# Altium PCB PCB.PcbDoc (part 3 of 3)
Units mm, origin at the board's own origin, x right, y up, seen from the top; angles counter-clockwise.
Board outline 120 x 100 mm, 4 copper layers (Top Layer, Mid-Layer 1, Mid-Layer 2, Bottom Layer); 85 components, 69 nets, 423 pads, 4470 vias.
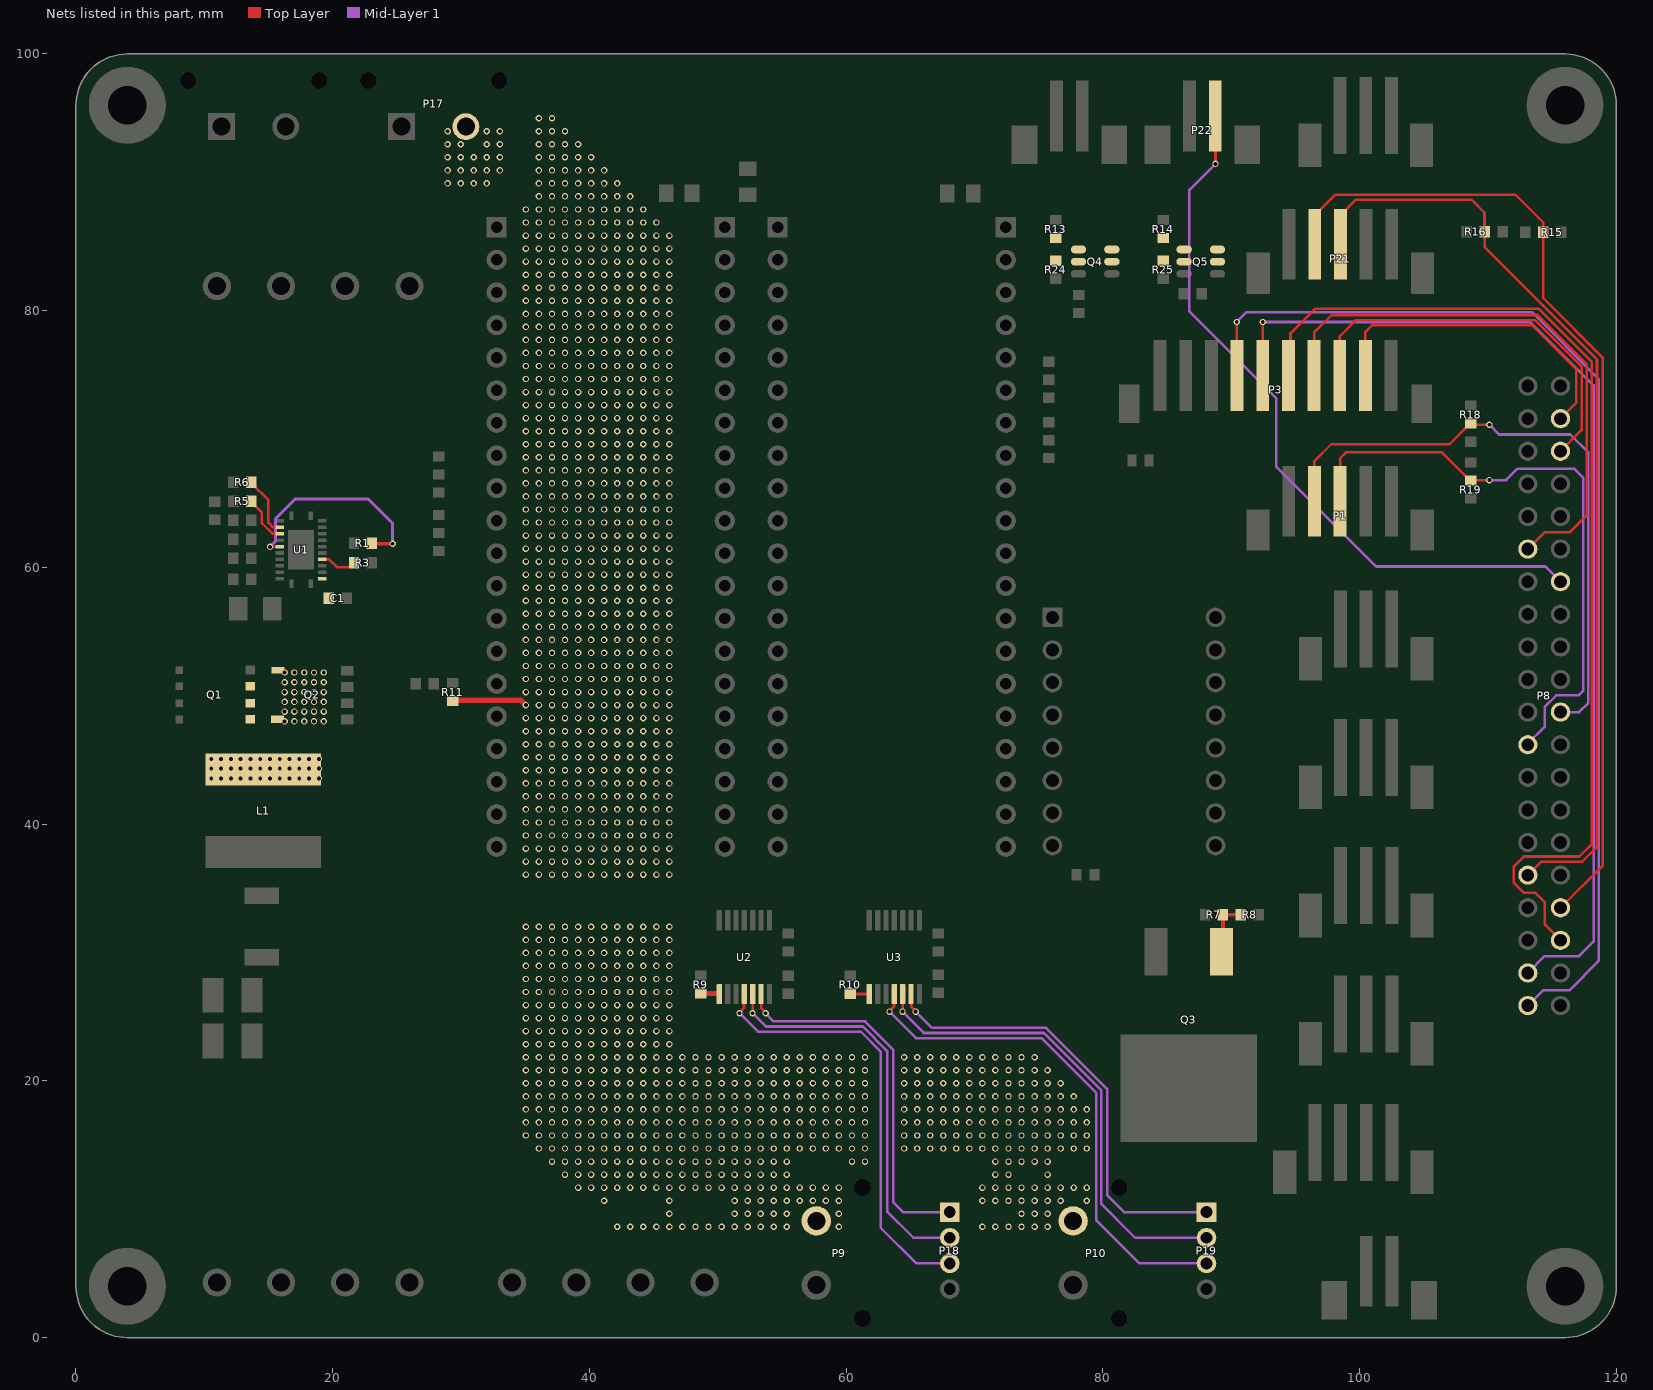
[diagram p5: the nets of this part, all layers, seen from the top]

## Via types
v1: diameter 0.5, hole 0.3, Top Layer to Bottom Layer, 4470 vias

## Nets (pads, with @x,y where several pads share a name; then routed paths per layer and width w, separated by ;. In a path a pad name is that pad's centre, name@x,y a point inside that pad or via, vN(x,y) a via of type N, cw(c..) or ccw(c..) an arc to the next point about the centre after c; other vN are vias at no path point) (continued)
NetQ3_1: Q3.1 R7.1 R8.2 | length 4.3
  Top Layer w0.3: Q3.1@89.23,30.071 89.346,30.187 R7.1@89.346,32.944 R8.2@90.74,32.944
NetQ4_1: Q4.1 Q4.2 Q4.5 Q4.6 R13.1 R24.2
NetQ5_1: Q5.1 Q5.2 Q5.5 Q5.6 R14.1 R25.1
NetR1_2: R1.2 U1.6 | length 16.9
  Top Layer w0.2: v1(15.113,61.595) 15.128,61.61 15.865,61.61 U1.6@15.88,61.626
  Top Layer w0.25: R1.2@23.052,61.874 23.077,61.9 23.128,61.849 v1(24.663,61.849)
  Mid-Layer 1 w0.25: v1(15.113,61.595) 15.545,62.027 15.545,63.805 17.069,65.329 22.758,65.329 24.663,63.424 v1(24.663,61.849)
NetR3_1: R3.1 U1.17 | length 2.8
  Top Layer w0.2: U1.17@19.195,60.626 19.714,60.626 20.32,60.02 21.322,60.02 R3.1@21.652,60.35
NetR5_1: R5.1 U1.4 | length 3.8
  Top Layer w0.2: R5.1@13.654,65.153 13.654,65.103 14.478,64.279 14.478,63.442 15.294,62.626 U1.4@15.88,62.626
NetR6_1: R6.1 U1.3 | length 4.7
  Top Layer w0.2: R6.1@13.654,66.627 13.654,66.577 14.986,65.245 14.986,63.5 15.36,63.126 U1.3@15.88,63.126
NetR9_1: R9.1 U2.8 | length 1.5
  Top Layer w0.4: R9.1@48.666,26.808 50.115,26.808 50.12,26.803 U2.8@50.12,26.772
NetR10_1: R10.1 U3.8 | length 1.5
  Top Layer w0.25: R10.1@60.325,26.783 60.336,26.772 U3.8@61.804,26.772
RSPI5_GPIO8: P1.3 P8.24 R19.1 | length 47.7
  Top Layer w0.2: P1.3@98.477,65.168 98.477,68.505 98.933,68.961 106.415,68.961 108.611,66.765 R19.1@108.661,66.765 108.698,66.802 v1(110.109,66.802)
  Mid-Layer 1 w0.2: v1(110.109,66.802) 111.42,66.802 112.309,67.691 116.713,67.691 117.424,66.98 117.424,50.419 117.043,50.038 115.316,50.038 114.427,49.149 114.427,47.625 113.106,46.304 P8.24@113.106,46.19
RSPI5_GPIO9: P1.4 P8.21 R18.1 | length 48.6
  Top Layer w0.2: P1.4@96.477,65.168 96.477,68.283 97.79,69.596 107,69.596 108.611,71.208 R18.1@108.661,71.208 108.749,71.12 v1(110.109,71.12)
  Mid-Layer 1 w0.2: v1(110.109,71.12) 110.871,70.358 116.408,70.358 117.824,68.942 117.824,49.447 117.107,48.73 P8.21@115.646,48.73
RSPI5_GPIO12: P8.32 P21.3 R16.1 | length 73.7
  Top Layer w0.2: P21.3@98.501,85.168 98.501,87.418 99.729,88.646 108.712,88.646 109.728,87.63 109.728,86.171 R16.1@109.742,86.157 109.742,84.949 118.491,76.2 118.491,72.853 118.491,38.227 117.343,37.079 114.155,37.079 P8.32@113.106,36.03
RSPI5_GPIO13: P8.33 P21.4 R15.1 | length 78.3
  Top Layer w0.2: P21.4@96.501,85.168 96.501,87.418 98.129,89.046 112.122,89.046 114.303,86.865 R15.1@114.303,86.106 114.303,80.972 118.948,76.327 118.948,36.792 P8.33@115.646,33.49
RSPI5_GPIO18: P3.4 P8.12 | length 44.2
  Top Layer w0.2: P3.4@96.451,74.954 96.451,78.29 97.828,79.667 113.856,79.667 117.691,75.832 117.691,64.046 116.396,62.751 114.427,62.751 P8.12@113.106,61.43
RSPI5_GPIO19: P3.5 P8.35 | length 81.5
  Top Layer w0.2: P3.5@94.451,74.954 94.615,75.117 94.615,78.232 96.52,80.137 113.97,80.137 118.091,76.016 118.091,38.462 117.108,37.479 112.79,37.479 112.014,36.703 112.014,35.433 112.801,34.646 113.69,34.646 114.427,33.909 114.427,32.169 P8.35@115.646,30.95
RSPI5_GPIO20: P3.6 P8.38 | length 81.4
  Top Layer w0.2: P3.6@92.451,74.954 92.456,74.958 v1(92.456,79.121)
  Mid-Layer 1 w0.2: v1(92.456,79.121) 113.284,79.121 118.224,74.181 118.224,30.848 117.094,29.718 114.414,29.718 P8.38@113.106,28.41
RSPI5_GPIO21: P3.7 P8.40 | length 87.1
  Top Layer w0.2: v1(90.424,79.121) 90.424,74.981 P3.7@90.449,74.955
  Mid-Layer 1 w0.2: v1(90.424,79.121) 91.186,79.883 113.411,79.883 118.624,74.67 118.624,29.343 116.332,27.051 114.287,27.051 P8.40@113.106,25.87
RSPI5_SCL: P3.3 P8.5 | length 31.2
  Top Layer w0.2: P3.3@98.451,74.954 98.451,78.004 99.714,79.267 113.671,79.267 117.291,75.647 117.291,70.695 P8.5@115.646,69.05
RSPI5_SDA: P3.2 P8.3 | length 25.8
  Top Layer w0.2: P3.2@100.451,74.954 100.451,78.353 100.965,78.867 113.436,78.867 116.891,75.412 116.891,72.835 P8.3@115.646,71.59
SERVO_X_GPIO_4: P18.3 U2.11 | length 34.1
  Top Layer w0.2: v1@51.689,25.336 52.04,25.687 U2.11@52.04,26.772
  Mid-Layer 1 w0.2: v1(51.689,25.273) 53.124,23.838 61.137,23.838 62.687,22.287 62.687,8.56 65.465,5.782 P18.3@68.072,5.782
SERVO_X_GPIO_11: P18.1 U2.13 | length 29.4
  Top Layer w0.2: U2.13@53.37,26.772 53.37,25.687 53.721,25.336 v1(53.721,25.273)
  Mid-Layer 1 w0.2: v1(53.721,25.273) 54.356,24.638 61.468,24.638 63.665,22.441 63.665,10.554 64.437,9.782 P18.1@68.072,9.782
SERVO_X_GPIO_12: P18.2 U2.12 | length 31.4
  Top Layer w0.2: v1(52.705,25.273) 52.713,25.281 52.713,26.764 U2.12@52.72,26.772
  Mid-Layer 1 w0.2: v1(52.705,25.273) 53.74,24.238 61.302,24.238 63.195,22.345 63.195,9.83 65.243,7.782 P18.2@68.072,7.782
SERVO_Y_GPIO_5: P19.3 U3.11 | length 40.2
  Top Layer w0.2: v1@63.373,25.463 63.724,25.814 U3.11@63.724,26.899
  Mid-Layer 1 w0.2: v1(63.373,25.4) 65.443,23.33 75.234,23.33 79.477,19.087 79.477,9.169 82.864,5.782 P19.3@88.072,5.782
SERVO_Y_GPIO_13: P19.1 U3.13 | length 35.6
  Top Layer w0.2: U3.13@65.054,26.899 U3.13@65.054,26.772 65.054,25.814 v1@65.405,25.463
  Mid-Layer 1 w0.2: v1(65.405,25.4) 66.675,24.13 75.565,24.13 80.327,19.368 80.327,11.113 81.658,9.782 P19.1@88.072,9.782
SERVO_Y_GPIO_14: P19.2 U3.12 | length 37.6
  Top Layer w0.2: v1@64.397,25.408 U3.12@64.397,26.891
  Mid-Layer 1 w0.2: v1(64.389,25.4) 66.059,23.73 75.399,23.73 79.883,19.246 79.883,10.414 82.515,7.782 P19.2@88.072,7.782
SHTDOWN_RSPI5_GPIO27: P8.13 P22.1 | length 56.8
  Top Layer w0.2: P22.1@88.752,95.168 88.773,95.147 v1(88.773,91.44)
  Mid-Layer 1 w0.2: v1(88.773,91.44) 86.741,89.408 86.741,79.941 93.491,73.191 93.491,67.857 101.277,60.071 114.465,60.071 P8.13@115.646,58.89
SW: C1.1 L1.1 Q1.1 Q1.2 Q1.3 Q2.5 Q2.6 U1.14
  other v1: 10.541,43.561 11.303,43.561 12.065,43.561 12.827,43.561 13.589,43.561 14.351,43.561 15.113,43.561 15.875,43.561 16.637,43.561 17.399,43.561 18.161,43.561 18.923,43.561 10.541,44.323 11.303,44.323 12.065,44.323 12.827,44.323 13.589,44.323 14.351,44.323 15.113,44.323 15.875,44.323 16.637,44.323 17.399,44.323 18.161,44.323 18.923,44.323 10.541,45.085 11.303,45.085 12.065,45.085 12.827,45.085 13.589,45.085 14.351,45.085 15.113,45.085 15.875,45.085 16.637,45.085 17.399,45.085 18.161,45.085 18.923,45.085 16.256,48.006 17.018,48.006 17.78,48.006 18.542,48.006 19.304,48.006 16.256,48.768 17.018,48.768 17.78,48.768 18.542,48.768 19.304,48.768 16.256,49.53 17.018,49.53 17.78,49.53 18.542,49.53 19.304,49.53 16.256,50.292 17.018,50.292 17.78,50.292 18.542,50.292 19.304,50.292 16.256,51.054 17.018,51.054 17.78,51.054 18.542,51.054 19.304,51.054 16.256,51.816 17.018,51.816 17.78,51.816 18.542,51.816 19.304,51.816
VIN_40V: P9.1 P10.1 P17.2 R11.2 | length 5.9
  Top Layer w0.4: R11.2@29.337,49.657 34.671,49.657 v1(35.052,49.276)
  other v1: 42.164,8.636 43.18,8.636 44.196,8.636 45.212,8.636 46.228,8.636 47.244,8.636 48.26,8.636 49.276,8.636 50.292,8.636 51.308,8.636 52.324,8.636 53.34,8.636 54.356,8.636 55.372,8.636 59.436,8.636 70.612,8.636 71.628,8.636 72.644,8.636 73.66,8.636 74.676,8.636 75.692,8.636 46.228,9.652 51.308,9.652 52.324,9.652 53.34,9.652 54.356,9.652 55.372,9.652 59.436,9.652 73.66,9.652 74.676,9.652 75.692,9.652 41.148,10.668 46.228,10.668 51.308,10.668 52.324,10.668 53.34,10.668 54.356,10.668 55.372,10.668 56.388,10.668 57.404,10.668 58.42,10.668 59.436,10.668 70.612,10.668 71.628,10.668 72.644,10.668 73.66,10.668 74.676,10.668 75.692,10.668 76.708,10.668 78.74,10.668 39.116,11.684 40.132,11.684 41.148,11.684 42.164,11.684 43.18,11.684 44.196,11.684 45.212,11.684 46.228,11.684 47.244,11.684 48.26,11.684 49.276,11.684 50.292,11.684 51.308,11.684 52.324,11.684 53.34,11.684 54.356,11.684 55.372,11.684 56.388,11.684 57.404,11.684 58.42,11.684 59.436,11.684 70.612,11.684 71.628,11.684 72.644,11.684 73.66,11.684 74.676,11.684 75.692,11.684 76.708,11.684 77.724,11.684 78.74,11.684 38.1,12.7 39.116,12.7 40.132,12.7 41.148,12.7 42.164,12.7 43.18,12.7 44.196,12.7 45.212,12.7 46.228,12.7 47.244,12.7 48.26,12.7 49.276,12.7 50.292,12.7 51.308,12.7 52.324,12.7 53.34,12.7 54.356,12.7 55.372,12.7 71.628,12.7 72.644,12.7 75.692,12.7 37.084,13.716 38.1,13.716 39.116,13.716 40.132,13.716 41.148,13.716 42.164,13.716 43.18,13.716 44.196,13.716 45.212,13.716 46.228,13.716 47.244,13.716 48.26,13.716 49.276,13.716 50.292,13.716 51.308,13.716 52.324,13.716 53.34,13.716 54.356,13.716 55.372,13.716 60.452,13.716 61.468,13.716 71.628,13.716 72.644,13.716 73.66,13.716 74.676,13.716 75.692,13.716 36.068,14.732 37.084,14.732 38.1,14.732 39.116,14.732 40.132,14.732 41.148,14.732 42.164,14.732 43.18,14.732 44.196,14.732 45.212,14.732 46.228,14.732 47.244,14.732 48.26,14.732 49.276,14.732 50.292,14.732 51.308,14.732 52.324,14.732 53.34,14.732 54.356,14.732 55.372,14.732 56.388,14.732 57.404,14.732 58.42,14.732 59.436,14.732 60.452,14.732 61.468,14.732 64.516,14.732 65.532,14.732 66.548,14.732 67.564,14.732 68.58,14.732 69.596,14.732 70.612,14.732 71.628,14.732 72.644,14.732 73.66,14.732 74.676,14.732 75.692,14.732 76.708,14.732 77.724,14.732 78.74,14.732 35.052,15.748 36.068,15.748 37.084,15.748 38.1,15.748 39.116,15.748 40.132,15.748 41.148,15.748 42.164,15.748 43.18,15.748 44.196,15.748 45.212,15.748 46.228,15.748 47.244,15.748 48.26,15.748 49.276,15.748 50.292,15.748 51.308,15.748 52.324,15.748 53.34,15.748 54.356,15.748 55.372,15.748 56.388,15.748 57.404,15.748 58.42,15.748 59.436,15.748 60.452,15.748 61.468,15.748 64.516,15.748 65.532,15.748 66.548,15.748 67.564,15.748 68.58,15.748 69.596,15.748 70.612,15.748 71.628,15.748 72.644,15.748 73.66,15.748 74.676,15.748 75.692,15.748 76.708,15.748 77.724,15.748 78.74,15.748 35.052,16.764 36.068,16.764 37.084,16.764 38.1,16.764 39.116,16.764 40.132,16.764 41.148,16.764 42.164,16.764 43.18,16.764 44.196,16.764 45.212,16.764 46.228,16.764 47.244,16.764 48.26,16.764 49.276,16.764 50.292,16.764 51.308,16.764 52.324,16.764 53.34,16.764 54.356,16.764 55.372,16.764 56.388,16.764 57.404,16.764 58.42,16.764 59.436,16.764 60.452,16.764 61.468,16.764 64.516,16.764 65.532,16.764 66.548,16.764 67.564,16.764 68.58,16.764 69.596,16.764 70.612,16.764 71.628,16.764 72.644,16.764 73.66,16.764 74.676,16.764 75.692,16.764 76.708,16.764 77.724,16.764 78.74,16.764 35.052,17.78 36.068,17.78 37.084,17.78 38.1,17.78 39.116,17.78 40.132,17.78 41.148,17.78 42.164,17.78 43.18,17.78 44.196,17.78 45.212,17.78 46.228,17.78 47.244,17.78 48.26,17.78 49.276,17.78 50.292,17.78 51.308,17.78 52.324,17.78 53.34,17.78 54.356,17.78 55.372,17.78 56.388,17.78 57.404,17.78 58.42,17.78 59.436,17.78 60.452,17.78 61.468,17.78 64.516,17.78 65.532,17.78 66.548,17.78 67.564,17.78 68.58,17.78 69.596,17.78 70.612,17.78 71.628,17.78 72.644,17.78 73.66,17.78 74.676,17.78 75.692,17.78 76.708,17.78 77.724,17.78 78.74,17.78 35.052,18.796 36.068,18.796 37.084,18.796 38.1,18.796 39.116,18.796 40.132,18.796 41.148,18.796 42.164,18.796 43.18,18.796 44.196,18.796 45.212,18.796 46.228,18.796 47.244,18.796 48.26,18.796 49.276,18.796 50.292,18.796 51.308,18.796 52.324,18.796 53.34,18.796 54.356,18.796 55.372,18.796 56.388,18.796 57.404,18.796 58.42,18.796 59.436,18.796 60.452,18.796 61.468,18.796 64.516,18.796 65.532,18.796 66.548,18.796 67.564,18.796 68.58,18.796 69.596,18.796 70.612,18.796 71.628,18.796 72.644,18.796 73.66,18.796 74.676,18.796 75.692,18.796 76.708,18.796 77.724,18.796 35.052,19.812 36.068,19.812 37.084,19.812 38.1,19.812 39.116,19.812 40.132,19.812 41.148,19.812 42.164,19.812 43.18,19.812 44.196,19.812 45.212,19.812 46.228,19.812 47.244,19.812 48.26,19.812 49.276,19.812 50.292,19.812 51.308,19.812 52.324,19.812 53.34,19.812 54.356,19.812 55.372,19.812 56.388,19.812 57.404,19.812 58.42,19.812 59.436,19.812 60.452,19.812 61.468,19.812 64.516,19.812 65.532,19.812 66.548,19.812 67.564,19.812 68.58,19.812 69.596,19.812 70.612,19.812 71.628,19.812 72.644,19.812 73.66,19.812 74.676,19.812 75.692,19.812 76.708,19.812 35.052,20.828 36.068,20.828 37.084,20.828 38.1,20.828 39.116,20.828 40.132,20.828 41.148,20.828 42.164,20.828 43.18,20.828 44.196,20.828 45.212,20.828 46.228,20.828 47.244,20.828 48.26,20.828 49.276,20.828 50.292,20.828 51.308,20.828 52.324,20.828 53.34,20.828 54.356,20.828 55.372,20.828 56.388,20.828 57.404,20.828 58.42,20.828 59.436,20.828 60.452,20.828 61.468,20.828 64.516,20.828 65.532,20.828 66.548,20.828 67.564,20.828 68.58,20.828 69.596,20.828 70.612,20.828 71.628,20.828 72.644,20.828 73.66,20.828 74.676,20.828 75.692,20.828 35.052,21.844 36.068,21.844 37.084,21.844 38.1,21.844 39.116,21.844 40.132,21.844 41.148,21.844 42.164,21.844 43.18,21.844 44.196,21.844 45.212,21.844 46.228,21.844 47.244,21.844 48.26,21.844 49.276,21.844 50.292,21.844 51.308,21.844 52.324,21.844 53.34,21.844 54.356,21.844 55.372,21.844 56.388,21.844 57.404,21.844 58.42,21.844 59.436,21.844 60.452,21.844 61.468,21.844 64.516,21.844 65.532,21.844 66.548,21.844 67.564,21.844 68.58,21.844 69.596,21.844 70.612,21.844 71.628,21.844 72.644,21.844 73.66,21.844 74.676,21.844 35.052,22.86 36.068,22.86 37.084,22.86 38.1,22.86 39.116,22.86 40.132,22.86 41.148,22.86 42.164,22.86 43.18,22.86 44.196,22.86 45.212,22.86 46.228,22.86 35.052,23.876 36.068,23.876 37.084,23.876 38.1,23.876 39.116,23.876 40.132,23.876 41.148,23.876 42.164,23.876 43.18,23.876 44.196,23.876 45.212,23.876 46.228,23.876 35.052,24.892 36.068,24.892 37.084,24.892 38.1,24.892 39.116,24.892 40.132,24.892 41.148,24.892 42.164,24.892 43.18,24.892 44.196,24.892 45.212,24.892 46.228,24.892 35.052,25.908 36.068,25.908 37.084,25.908 38.1,25.908 39.116,25.908 40.132,25.908 41.148,25.908 42.164,25.908 43.18,25.908 44.196,25.908 45.212,25.908 46.228,25.908 35.052,26.924 36.068,26.924 37.084,26.924 38.1,26.924 39.116,26.924 40.132,26.924 41.148,26.924 42.164,26.924 43.18,26.924 44.196,26.924 45.212,26.924 46.228,26.924 35.052,27.94 36.068,27.94 37.084,27.94 38.1,27.94 39.116,27.94 40.132,27.94 41.148,27.94 42.164,27.94 43.18,27.94 44.196,27.94 45.212,27.94 46.228,27.94 35.052,28.956 36.068,28.956 37.084,28.956 38.1,28.956 39.116,28.956 40.132,28.956 41.148,28.956 42.164,28.956 43.18,28.956 44.196,28.956 45.212,28.956 46.228,28.956 35.052,29.972 36.068,29.972 37.084,29.972 38.1,29.972 39.116,29.972 40.132,29.972 41.148,29.972 42.164,29.972 43.18,29.972 44.196,29.972 45.212,29.972 46.228,29.972 35.052,30.988 36.068,30.988 37.084,30.988 38.1,30.988 39.116,30.988 40.132,30.988 41.148,30.988 42.164,30.988 43.18,30.988 44.196,30.988 45.212,30.988 46.228,30.988 35.052,32.004 36.068,32.004 37.084,32.004 38.1,32.004 39.116,32.004 40.132,32.004 41.148,32.004 42.164,32.004 43.18,32.004 44.196,32.004 45.212,32.004 46.228,32.004 35.052,36.068 36.068,36.068 37.084,36.068 38.1,36.068 39.116,36.068 40.132,36.068 41.148,36.068 42.164,36.068 43.18,36.068 44.196,36.068 45.212,36.068 46.228,36.068 35.052,37.084 36.068,37.084 37.084,37.084 38.1,37.084 39.116,37.084 40.132,37.084 41.148,37.084 42.164,37.084 43.18,37.084 44.196,37.084 45.212,37.084 46.228,37.084 35.052,38.1 36.068,38.1 37.084,38.1 38.1,38.1 39.116,38.1 40.132,38.1 41.148,38.1 42.164,38.1 43.18,38.1 44.196,38.1 45.212,38.1 46.228,38.1 35.052,39.116 36.068,39.116 37.084,39.116 38.1,39.116 39.116,39.116 40.132,39.116 41.148,39.116 42.164,39.116 43.18,39.116 44.196,39.116 45.212,39.116 46.228,39.116 35.052,40.132 36.068,40.132 37.084,40.132 38.1,40.132 39.116,40.132 40.132,40.132 41.148,40.132 42.164,40.132 43.18,40.132 44.196,40.132 45.212,40.132 46.228,40.132 35.052,41.148 36.068,41.148 37.084,41.148 38.1,41.148 39.116,41.148 40.132,41.148 41.148,41.148 42.164,41.148 43.18,41.148 44.196,41.148 45.212,41.148 46.228,41.148 35.052,42.164 36.068,42.164 37.084,42.164 38.1,42.164 39.116,42.164 40.132,42.164 41.148,42.164 42.164,42.164 43.18,42.164 44.196,42.164 45.212,42.164 46.228,42.164 35.052,43.18 36.068,43.18 37.084,43.18 38.1,43.18 39.116,43.18 40.132,43.18 41.148,43.18 42.164,43.18 43.18,43.18 44.196,43.18 45.212,43.18 46.228,43.18 35.052,44.196 36.068,44.196 37.084,44.196 38.1,44.196 39.116,44.196 40.132,44.196 41.148,44.196 42.164,44.196 43.18,44.196 44.196,44.196 45.212,44.196 46.228,44.196 35.052,45.212 36.068,45.212 37.084,45.212 38.1,45.212 39.116,45.212 40.132,45.212 41.148,45.212 42.164,45.212 43.18,45.212 44.196,45.212 45.212,45.212 46.228,45.212 35.052,46.228 36.068,46.228 37.084,46.228 38.1,46.228 39.116,46.228 40.132,46.228 41.148,46.228 42.164,46.228 43.18,46.228 44.196,46.228 45.212,46.228 46.228,46.228 35.052,47.244 36.068,47.244 37.084,47.244 38.1,47.244 39.116,47.244 40.132,47.244 41.148,47.244 42.164,47.244 43.18,47.244 44.196,47.244 45.212,47.244 46.228,47.244 35.052,48.26 36.068,48.26 37.084,48.26 38.1,48.26 39.116,48.26 40.132,48.26 41.148,48.26 42.164,48.26 43.18,48.26 44.196,48.26 45.212,48.26 46.228,48.26 36.068,49.276 37.084,49.276 38.1,49.276 39.116,49.276 40.132,49.276 41.148,49.276 42.164,49.276 43.18,49.276 44.196,49.276 45.212,49.276 46.228,49.276 35.052,50.292 36.068,50.292 37.084,50.292 38.1,50.292 39.116,50.292 40.132,50.292 41.148,50.292 42.164,50.292 43.18,50.292 44.196,50.292 45.212,50.292 46.228,50.292 35.052,51.308 36.068,51.308 37.084,51.308 38.1,51.308 39.116,51.308 40.132,51.308 41.148,51.308 42.164,51.308 43.18,51.308 44.196,51.308 45.212,51.308 46.228,51.308 35.052,52.324 36.068,52.324 37.084,52.324 38.1,52.324 39.116,52.324 40.132,52.324 41.148,52.324 42.164,52.324 43.18,52.324 44.196,52.324 45.212,52.324 46.228,52.324 35.052,53.34 36.068,53.34 37.084,53.34 38.1,53.34 39.116,53.34 40.132,53.34 41.148,53.34 42.164,53.34 43.18,53.34 44.196,53.34 45.212,53.34 46.228,53.34 35.052,54.356 36.068,54.356 37.084,54.356 38.1,54.356 39.116,54.356 40.132,54.356 41.148,54.356 42.164,54.356 43.18,54.356 44.196,54.356 45.212,54.356 46.228,54.356 35.052,55.372 36.068,55.372 37.084,55.372 38.1,55.372 39.116,55.372 40.132,55.372 41.148,55.372 42.164,55.372 43.18,55.372 44.196,55.372 45.212,55.372 46.228,55.372 35.052,56.388 36.068,56.388 37.084,56.388 38.1,56.388 39.116,56.388 40.132,56.388 41.148,56.388 42.164,56.388 43.18,56.388 44.196,56.388 45.212,56.388 46.228,56.388 35.052,57.404 36.068,57.404 37.084,57.404 38.1,57.404 39.116,57.404 40.132,57.404 41.148,57.404 42.164,57.404 43.18,57.404 44.196,57.404 45.212,57.404 46.228,57.404 35.052,58.42 36.068,58.42 37.084,58.42 38.1,58.42 39.116,58.42 40.132,58.42 41.148,58.42 42.164,58.42 43.18,58.42 44.196,58.42 45.212,58.42 46.228,58.42 35.052,59.436 36.068,59.436 37.084,59.436 38.1,59.436 39.116,59.436 40.132,59.436 41.148,59.436 42.164,59.436 43.18,59.436 44.196,59.436 45.212,59.436 46.228,59.436 35.052,60.452 36.068,60.452 37.084,60.452 38.1,60.452 39.116,60.452 40.132,60.452 41.148,60.452 42.164,60.452 43.18,60.452 44.196,60.452 45.212,60.452 46.228,60.452 35.052,61.468 36.068,61.468 37.084,61.468 38.1,61.468 39.116,61.468 40.132,61.468 41.148,61.468 42.164,61.468 43.18,61.468 44.196,61.468 45.212,61.468 46.228,61.468 35.052,62.484 36.068,62.484 37.084,62.484 38.1,62.484 39.116,62.484 40.132,62.484 41.148,62.484 42.164,62.484 43.18,62.484 44.196,62.484 45.212,62.484 46.228,62.484 35.052,63.5 36.068,63.5 37.084,63.5 38.1,63.5 39.116,63.5 40.132,63.5 41.148,63.5 42.164,63.5 43.18,63.5 44.196,63.5 45.212,63.5 46.228,63.5 35.052,64.516 36.068,64.516 37.084,64.516 38.1,64.516 39.116,64.516 40.132,64.516 41.148,64.516 42.164,64.516 43.18,64.516 44.196,64.516 45.212,64.516 46.228,64.516 35.052,65.532 36.068,65.532 37.084,65.532 38.1,65.532 39.116,65.532 40.132,65.532 41.148,65.532 42.164,65.532 43.18,65.532 44.196,65.532 45.212,65.532 46.228,65.532 35.052,66.548 36.068,66.548 37.084,66.548 38.1,66.548 39.116,66.548 40.132,66.548 41.148,66.548 42.164,66.548 43.18,66.548 44.196,66.548 45.212,66.548 46.228,66.548 35.052,67.564 36.068,67.564 37.084,67.564 38.1,67.564 39.116,67.564 40.132,67.564 41.148,67.564 42.164,67.564 43.18,67.564 44.196,67.564 45.212,67.564 46.228,67.564 35.052,68.58 36.068,68.58 37.084,68.58 38.1,68.58 39.116,68.58 40.132,68.58 41.148,68.58 42.164,68.58 43.18,68.58 44.196,68.58 45.212,68.58 46.228,68.58 35.052,69.596 36.068,69.596 37.084,69.596 38.1,69.596 39.116,69.596 40.132,69.596 41.148,69.596 42.164,69.596 43.18,69.596 44.196,69.596 45.212,69.596 46.228,69.596 35.052,70.612 36.068,70.612 37.084,70.612 38.1,70.612 39.116,70.612 40.132,70.612 41.148,70.612 42.164,70.612 43.18,70.612 44.196,70.612 45.212,70.612 46.228,70.612 35.052,71.628 36.068,71.628 37.084,71.628 38.1,71.628 39.116,71.628 40.132,71.628 41.148,71.628 42.164,71.628 43.18,71.628 44.196,71.628 45.212,71.628 46.228,71.628 35.052,72.644 36.068,72.644 37.084,72.644 38.1,72.644 39.116,72.644 40.132,72.644 41.148,72.644 42.164,72.644 43.18,72.644 44.196,72.644 45.212,72.644 46.228,72.644 35.052,73.66 36.068,73.66 37.084,73.66 38.1,73.66 39.116,73.66 40.132,73.66 41.148,73.66 42.164,73.66 43.18,73.66 44.196,73.66 45.212,73.66 46.228,73.66 35.052,74.676 36.068,74.676 37.084,74.676 38.1,74.676 39.116,74.676 40.132,74.676 41.148,74.676 42.164,74.676 43.18,74.676 44.196,74.676 45.212,74.676 46.228,74.676 35.052,75.692 36.068,75.692 37.084,75.692 38.1,75.692 39.116,75.692 40.132,75.692 41.148,75.692 42.164,75.692 43.18,75.692 44.196,75.692 45.212,75.692 46.228,75.692 35.052,76.708 36.068,76.708 37.084,76.708 38.1,76.708 39.116,76.708 40.132,76.708 41.148,76.708 42.164,76.708 43.18,76.708 44.196,76.708 45.212,76.708 46.228,76.708 35.052,77.724 36.068,77.724 37.084,77.724 38.1,77.724 39.116,77.724 40.132,77.724 41.148,77.724 42.164,77.724 43.18,77.724 44.196,77.724 45.212,77.724 46.228,77.724 35.052,78.74 36.068,78.74 37.084,78.74 38.1,78.74 39.116,78.74 40.132,78.74 41.148,78.74 42.164,78.74 43.18,78.74 44.196,78.74 45.212,78.74 46.228,78.74 35.052,79.756 36.068,79.756 37.084,79.756 38.1,79.756 39.116,79.756 40.132,79.756 41.148,79.756 42.164,79.756 43.18,79.756 44.196,79.756 45.212,79.756 46.228,79.756 35.052,80.772 36.068,80.772 37.084,80.772 38.1,80.772 39.116,80.772 40.132,80.772 41.148,80.772 42.164,80.772 43.18,80.772 44.196,80.772 45.212,80.772 46.228,80.772 35.052,81.788 36.068,81.788 37.084,81.788 38.1,81.788 39.116,81.788 40.132,81.788 41.148,81.788 42.164,81.788 43.18,81.788 44.196,81.788 45.212,81.788 46.228,81.788 35.052,82.804 36.068,82.804 37.084,82.804 38.1,82.804 39.116,82.804 40.132,82.804 41.148,82.804 42.164,82.804 43.18,82.804 44.196,82.804 45.212,82.804 46.228,82.804 35.052,83.82 36.068,83.82 37.084,83.82 38.1,83.82 39.116,83.82 40.132,83.82 41.148,83.82 42.164,83.82 43.18,83.82 44.196,83.82 45.212,83.82 46.228,83.82 35.052,84.836 36.068,84.836 37.084,84.836 38.1,84.836 39.116,84.836 40.132,84.836 41.148,84.836 42.164,84.836 43.18,84.836 44.196,84.836 45.212,84.836 46.228,84.836 35.052,85.852 36.068,85.852 37.084,85.852 38.1,85.852 39.116,85.852 40.132,85.852 41.148,85.852 42.164,85.852 43.18,85.852 44.196,85.852 45.212,85.852 46.228,85.852 35.052,86.868 36.068,86.868 37.084,86.868 38.1,86.868 39.116,86.868 40.132,86.868 41.148,86.868 42.164,86.868 43.18,86.868 44.196,86.868 45.212,86.868 35.052,87.884 36.068,87.884 37.084,87.884 38.1,87.884 39.116,87.884 40.132,87.884 41.148,87.884 42.164,87.884 43.18,87.884 44.196,87.884 36.068,88.9 37.084,88.9 38.1,88.9 39.116,88.9 40.132,88.9 41.148,88.9 42.164,88.9 43.18,88.9 28.956,89.916 29.972,89.916 30.988,89.916 32.004,89.916 36.068,89.916 37.084,89.916 38.1,89.916 39.116,89.916 40.132,89.916 41.148,89.916 42.164,89.916 28.956,90.932 29.972,90.932 30.988,90.932 32.004,90.932 33.02,90.932 36.068,90.932 37.084,90.932 38.1,90.932 39.116,90.932 40.132,90.932 41.148,90.932 28.956,91.948 29.972,91.948 30.988,91.948 32.004,91.948 33.02,91.948 36.068,91.948 37.084,91.948 38.1,91.948 39.116,91.948 40.132,91.948 28.956,92.964 29.972,92.964 32.004,92.964 33.02,92.964 36.068,92.964 37.084,92.964 38.1,92.964 39.116,92.964 28.956,93.98 32.004,93.98 33.02,93.98 36.068,93.98 37.084,93.98 38.1,93.98 36.068,94.996 37.084,94.996
pads on no net: MOD1.1 MOD1.2 MOD1.3 MOD1.4 MOD1.5 MOD2.16 MOD2.17 MOD2.20 MOD2.21 MOD2.22 MOD2.24 MOD2.25 MOD2.29 MOD2.30 MOD2.31 MOD2.32 MOD2.34 MOD2.35 MOD2.37 MOD2.40 MOD3.1 MOD3.2 MOD3.4 MOD3.5 MOD3.6 MOD3.7 MOD3.9 MOD3.10 MOD3.11 MOD3.12 MOD3.14 MOD3.15 MOD3.19 MOD3.20 MOD3.21 MOD3.22 MOD3.24 MOD3.25 MOD3.26 MOD3.27 MOD3.29 MOD3.30 MOD3.31 MOD3.32 MOD3.36 MOD3.37 MOD3.40 P7. P8.11 P8.16 P8.17 P8.18 P8.19 P8.22 P8.23 P8.26 P8.27 P8.28 P8.31 P8.36 P8.37 P9. P10. P17. P21.MP U1.2 U1.22 U1.23 U2.5 U2.6 U2.9 U2.10 U3.5 U3.6 U3.9 U3.10

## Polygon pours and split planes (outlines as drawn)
GND on Top Layer "Top Layer-GND" (solid, pour order 2): 115.849,0.027 ccw(c115.849,4.089) 119.911,4.089 119.969,95.809 ccw(c115.861,95.918) 115.97,100.025 3.984,100.025 ccw(c3.979,96.021) -0.025,96.025 -0.025,4.089 ccw(c4.039,4.089) 4.039,0.025
GND on Mid-Layer 1 "Mid-Layer 1-GND" (solid, pour order 4): 115.863,0.002 ccw(c115.863,4.064) 119.925,4.064 119.983,95.783 ccw(c115.875,95.892) 115.984,100 3.998,100 ccw(c3.993,95.996) -0.011,96 -0.011,4.064 ccw(c4.053,4.064) 4.053,0
GND on Bottom Layer "Bottom Layer-GND" (solid, pour order 6): 115.863,0.002 ccw(c115.863,4.064) 119.925,4.064 119.983,95.783 ccw(c115.875,95.892) 115.984,100 3.998,100 ccw(c3.993,95.996) -0.011,96 -0.011,4.064 ccw(c4.053,4.064) 4.053,0
+5V on Mid-Layer 2 "Mid-Layer 2-+5V" (solid, pour order 0): 115.853,0.012 ccw(c115.853,4.074) 119.915,4.074 119.973,95.793 ccw(c115.865,95.902) 115.974,100.01 3.988,100.01 ccw(c3.983,96.006) -0.021,96.01 -0.021,4.074 ccw(c4.043,4.074) 4.043,0.01

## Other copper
Top Layer:
  region net +5V: 103.149,95.809 103.149,92.024 101.727,92.024 101.727,98.425 105.029,98.425 105.029,95.809
  region net +5V: 103.048,85.7 103.048,82.372 101.854,82.372 101.854,88.214 105.156,88.214 105.156,85.7
  region net +5V: 103.022,75.692 103.022,72.136 101.6,72.136 101.6,78.308 104.902,78.308 104.902,75.692
  region net +5V: 103.276,65.532 103.276,62.23 101.854,62.23 101.854,68.148 105.156,68.148 105.156,65.532
  region net +5V: 103.276,55.88 103.276,52.07 101.854,52.07 101.854,58.496 105.156,58.496 105.156,55.88
  region net +5V: 103.276,45.72 103.276,42.164 101.854,42.164 101.854,48.336 105.156,48.336 105.156,45.72
  region net +5V: 103.276,36.068 103.276,32.004 101.854,32.004 101.854,38.684 105.156,38.684 105.156,36.068
  region net +5V: 103.276,25.654 103.276,22.098 101.854,22.098 101.854,28.27 105.156,28.27 105.156,25.654
  region net +5V: 103.022,5.334 103.022,2.413 101.6,2.413 101.6,7.95 104.902,7.95 104.902,5.334
  region net NetF1_1: 85.598,77.724 85.598,67.564 83.058,67.564 83.058,70.866 83.058,77.724
  region net +5V: 12.192,17.78 8.89,14.478 8.89,4.064 10.16,2.794 28.194,2.794 28.194,12.192 22.606,17.78 22.606,28.448 16.764,28.448 16.51,28.702 16.51,30.988 12.192,30.988
  region net NetL1_2: 20.574,39.624 20.574,32.512 8.89,32.512 8.89,39.624
  region net SW: 9.906,45.72 10.414,46.228 12.7,46.228 13.208,46.736 13.208,51.308 14.224,51.308 15.125,52.209 15.125,52.463 18.669,56.007 18.669,59.258 19.736,59.258 20.32,58.674 20.32,42.672 9.906,42.672
  region net NetQ5_1: 89.662,83.439 85.852,83.439 84.074,83.439 84.074,86.106 89.662,86.106
  region net NetQ4_1: 81.407,83.439 77.597,83.439 75.819,83.439 75.819,86.106 81.407,86.106
  region net NetP13_2: 81.153,23.876 92.837,23.876 92.837,11.049 94.234,9.652 101.219,9.652 101.219,2.159 99.314,2.159 99.314,4.445 99.06,4.699 91.301,4.699 89.154,6.846 89.154,10.668 89.027,10.795 85.471,10.795 81.153,15.113
  region net VIN_40V: 28.448,95.377 37.465,95.377 46.736,86.106 46.736,22.352 74.676,22.352 79.248,17.78 79.248,7.874 70.358,7.874 70.358,11.938 69.342,13.208 61.214,13.208 59.944,11.938 59.944,7.874 41.91,7.874 34.544,15.24 34.544,88.392 28.448,88.392
  region net +BATT: 14.986,52.832 16.764,54.61 16.764,56.896 17.526,57.658 17.526,59.182 16.51,59.182 16.51,58.42 16.256,58.166 14.732,58.166 14.478,57.912 14.478,55.626 13.97,55.118 11.176,55.118 9.906,56.388 9.906,69.088 18.288,77.47 18.288,81.28 27.178,90.17 27.178,95.504 18.415,95.504 18.415,92.202 13.97,92.202 13.97,95.504 8.382,95.504 0.762,87.884 0.762,49.022 3.048,46.736 12.7,46.736 12.7,52.832
Bottom Layer:
  region net NetL1_2: 20.574,39.624 20.574,32.512 8.89,32.512 8.89,39.624
  region net SW: 9.906,45.72 10.414,46.228 12.7,46.228 13.208,46.736 13.208,51.308 14.224,51.308 15.125,52.209 15.125,52.463 18.669,56.007 18.669,56.388 20.32,56.388 20.32,42.672 9.906,42.672
  region net VIN_40V: 28.448,95.377 37.465,95.377 46.736,86.106 46.736,22.352 74.676,22.352 79.248,17.78 79.248,7.874 70.358,7.874 70.358,11.938 69.342,13.208 61.214,13.208 59.944,11.938 59.944,7.874 41.91,7.874 34.544,15.24 34.544,88.392 28.448,88.392
  region net +BATT: 13.97,55.118 13.97,52.832 12.7,52.832 12.7,46.736 3.048,46.736 0.762,49.022 0.762,87.884 8.382,95.504 13.97,95.504 13.97,92.202 18.415,92.202 18.415,95.504 27.178,95.504 27.178,90.17 18.288,81.28 18.288,77.47 9.906,69.088 9.906,56.388 11.176,55.118

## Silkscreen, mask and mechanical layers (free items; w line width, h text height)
Top Overlay:
  text "GND" at 95.807,98.384 h1.5
  text "IO37" at 99.129,98.384 h1.5
  text "5V" at 101.978,98.384 h1.5
  text "GND" at 74.115,98.105 h1.5
  text "IN1" at 77.86,98.105 h1.5
  text "GND" at 84.479,98.105 h1.5
  text "IO27" at 88.233,98.105 h1.5
  text "TRIG-SERVO" at 107.112,90.104 h1.5 r90
  text "E-STOP" at 34.874,89.887 h1.5 r90
  text "BATTERY-IN" at 20.777,89.87 h1.5 r90
  text "START-SW" at 73.88,89.179 h1.5
  text "STOP-SW" at 84.703,89.179 h1.5
  text "+BATT" at 9.205,88.646 h1.5
  text "GND" at 14.919,88.646 h1.5
  text "+B-IN" at 23.686,88.646 h1.5
  text "+B-OUT" at 27.821,88.646 h1.5
  text "GND" at 91.184,88.174 h1.5
  text "IO13" at 94.308,88.173 h1.5
  text "IO12" at 97.433,88.173 h1.5
  text "GND" at 100.684,88.173 h1.5
  text "5V" at 103.832,88.173 h1.5
  text "UART-4" at 107.112,80.223 h1.5 r90
  text "+BT" at 80.646,77.886 h1.5
  text "GND" at 83.564,77.886 h1.5
  text "GND" at 86.688,77.886 h1.5
  text "IO20" at 89.66,77.886 h1.5
  text "IO19" at 92.781,77.886 h1.5
  text "IO18" at 95.883,77.886 h1.5
  text "SCL" at 98.779,77.886 h1.5
  text "SDA" at 101.751,77.886 h1.5
  text "5V" at 104.747,77.887 h1.5
  text "GND" at 19.072,76.2 h2
  text "+BAT" at 8.653,76.175 h2
  text "+BAT" at 13.653,76.175 h2
  text "GND" at 24.072,76.149 h2
  text "RSPI5-IO" at 106.934,70.232 h1.5 r90
  text "GND" at 90.88,68.132 h1.5
  text "IO9" at 94.309,68.132 h1.5
  text "IO8" at 97.433,68.132 h1.5
  text "GND" at 100.684,68.132 h1.5
  text "5V" at 103.832,68.133 h1.5
  text "AI-MOD" at 107.112,60.386 h1.5 r90
  text "GND" at 95.807,58.404 h1.5
  text "IO39" at 99.084,58.404 h1.5
  text "5V" at 102.562,58.404 h1.5
  text "HIT-SENSOR" at 107.112,50.223 h1.5 r90
  text "GND" at 95.807,48.397 h1.5
  text "IO35" at 99.084,48.397 h1.5
  text "5V" at 102.562,48.397 h1.5
  text "CAM-LIMIT" at 107.112,40.212 h1.5 r90
  text "GND" at 95.807,38.567 h1.5
  text "IO33" at 99.084,38.567 h1.5
  text "5V" at 102.562,38.567 h1.5
  text "X-LIMIT" at 107.112,30.256 h1.5 r90
  text "GND" at 95.807,28.484 h1.5
  text "IO34" at 99.084,28.484 h1.5
  text "5V" at 102.562,28.484 h1.5
  text "Y-LIMIT" at 107.112,20.247 h1.5 r90
  text "2B" at 94.994,18.552 h1.5
  text "2A" at 97.077,18.552 h1.5
  text "1A" at 99.084,18.552 h1.5
  text "1B" at 101.687,18.552 h1.5
  text "BATT" at 54.818,12.7 h1.5
  text "X-SERVO" at 65.054,12.7 h1.5
  text "BATT" at 74.859,12.7 h1.5
  text "Y-SERVO" at 84.993,12.7 h1.5
  text "CAM-SERVO" at 107.112,10.338 h1.5 r90
  text "+5V" at 19.072,9.373 h2
  text "+5V" at 8.653,9.348 h2
  text "+5V" at 13.653,9.348 h2
  text "+5V" at 24.072,9.322 h2
  text "GND" at 31.653,9.322 h2
  text "GND" at 36.653,9.322 h2
  text "GND" at 42.072,9.322 h2
  text "GND" at 47.072,9.322 h2
  text "IO11" at 70.38,9.284 h1.5
  text "IO13" at 90.391,9.284 h1.5
  text "GND" at 98.753,8.164 h1.5
  text "5V" at 101.687,8.164 h1.5
  text "IO12" at 70.381,7.275 h1.5
  text "IO14" at 90.453,7.274 h1.5
  text "+BAT" at 64.262,6.769 h2 r90
  text "+BAT" at 84.404,6.769 h2 r90
  text "IO4" at 70.271,5.284 h1.5
  text "IO5" at 90.362,5.284 h1.5
  text "GND" at 70.458,3.284 h1.5
  text "GND" at 90.448,3.287 h1.5
  text "GND" at 64.262,1.769 h2 r90
  text "GND" at 84.404,1.769 h2 r90
  text "LASER" at 107.239,0.246 h1.5 r90
Mechanical 1:
  the board outline again, w0.2

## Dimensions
116,0 to 116,100 on Mechanical 2
0,4 to 120,4 on Mechanical 2
4,96 to 4,4 on Mechanical 2
4,96 to 116,96 on Mechanical 2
